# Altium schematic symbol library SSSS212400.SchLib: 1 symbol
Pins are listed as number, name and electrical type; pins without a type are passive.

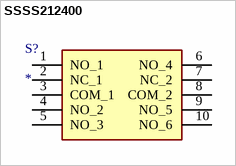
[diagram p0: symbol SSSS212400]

## SSSS212400
designator S?
Switch; Manufacturer_Name: ALPS Electric; Manufacturer_Part_Number: SSSS212400
footprint SSSS212400
pins: 1 NO_1, 2 NC_1, 3 COM_1, 4 NO_2, 5 NO_3, 6 NO_4, 7 NC_2, 8 COM_2, 9 NO_5, 10 NO_6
